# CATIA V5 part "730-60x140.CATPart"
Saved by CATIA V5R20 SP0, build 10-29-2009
Part number: 730-60x140
Definition: NONE
Nomenclature: 730-60x140
Source: Unknown
Description: 730-60x140
Bounding box of the stored display mesh (mm): x -34 to 34, y -33.316 to 33.316, z 0 to 140
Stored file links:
  C:\Users\Utente\Desktop\IO LAVORO\3D X SITO CF\X SITO\730\730-60x140.CATPart
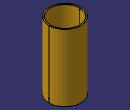
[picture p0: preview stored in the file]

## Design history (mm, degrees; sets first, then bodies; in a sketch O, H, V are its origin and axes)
Body1 "730-60x140" (main body)
  Solid1: solid without history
